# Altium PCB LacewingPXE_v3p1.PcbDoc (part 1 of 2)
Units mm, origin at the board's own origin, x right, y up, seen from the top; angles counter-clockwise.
Board outline 62.74 x 108.59 mm, 2 copper layers (Top Layer, Bottom Layer); 114 components, 91 nets, 539 pads, 84 vias.
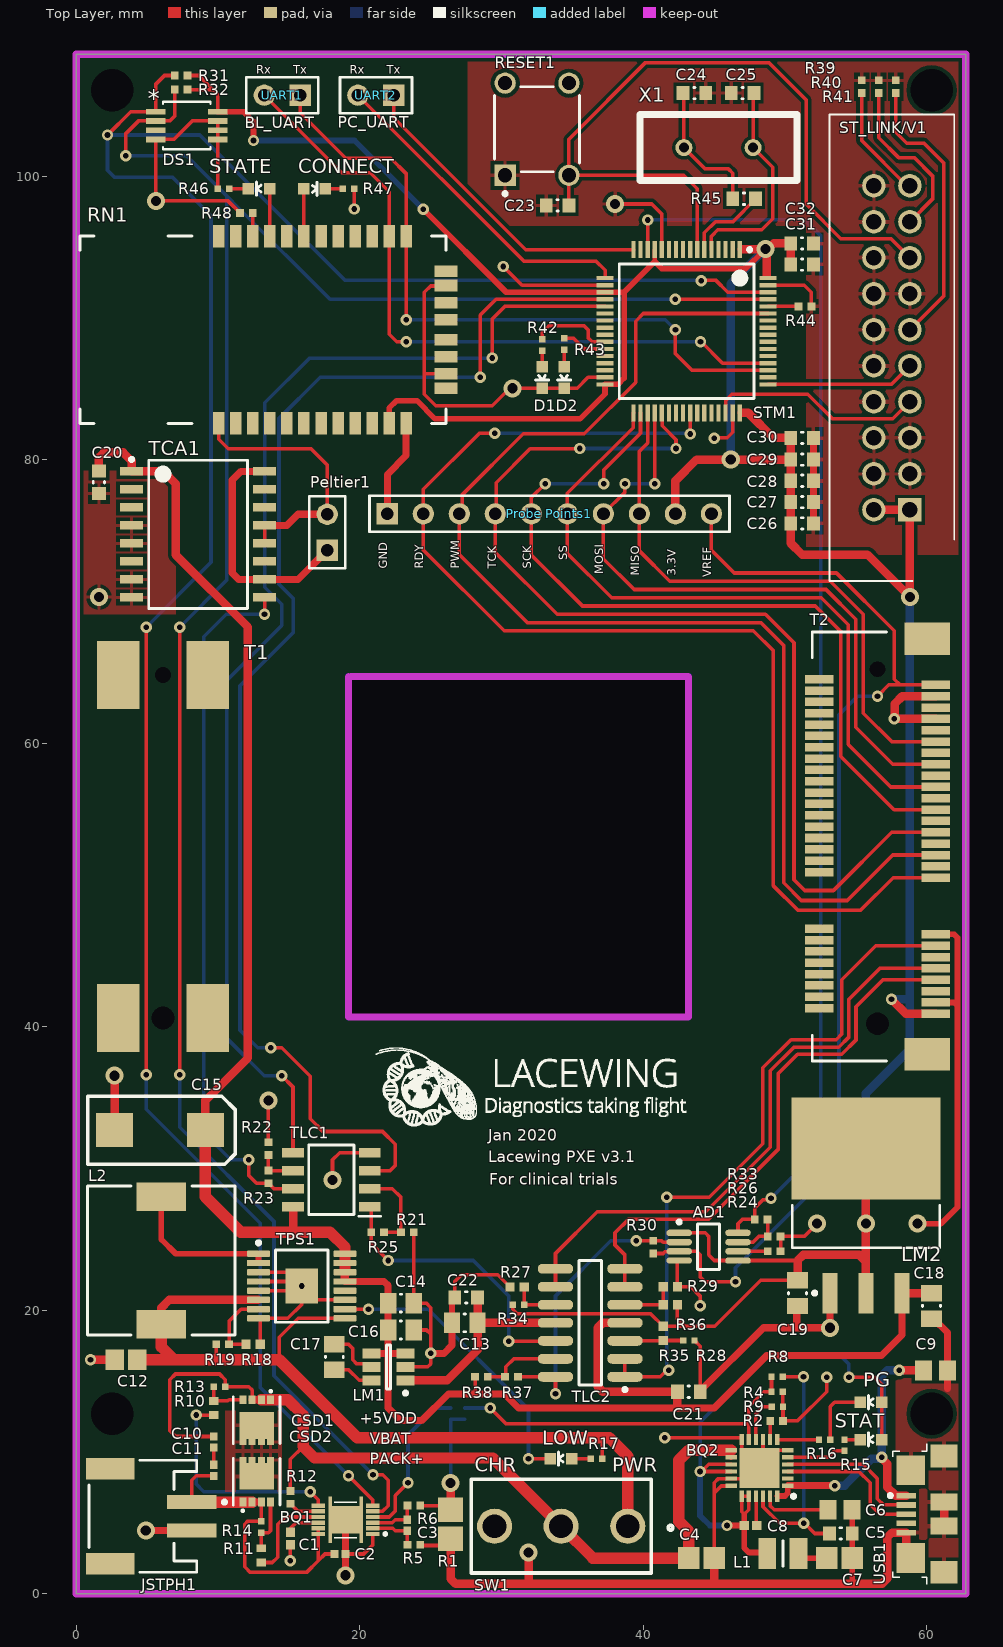
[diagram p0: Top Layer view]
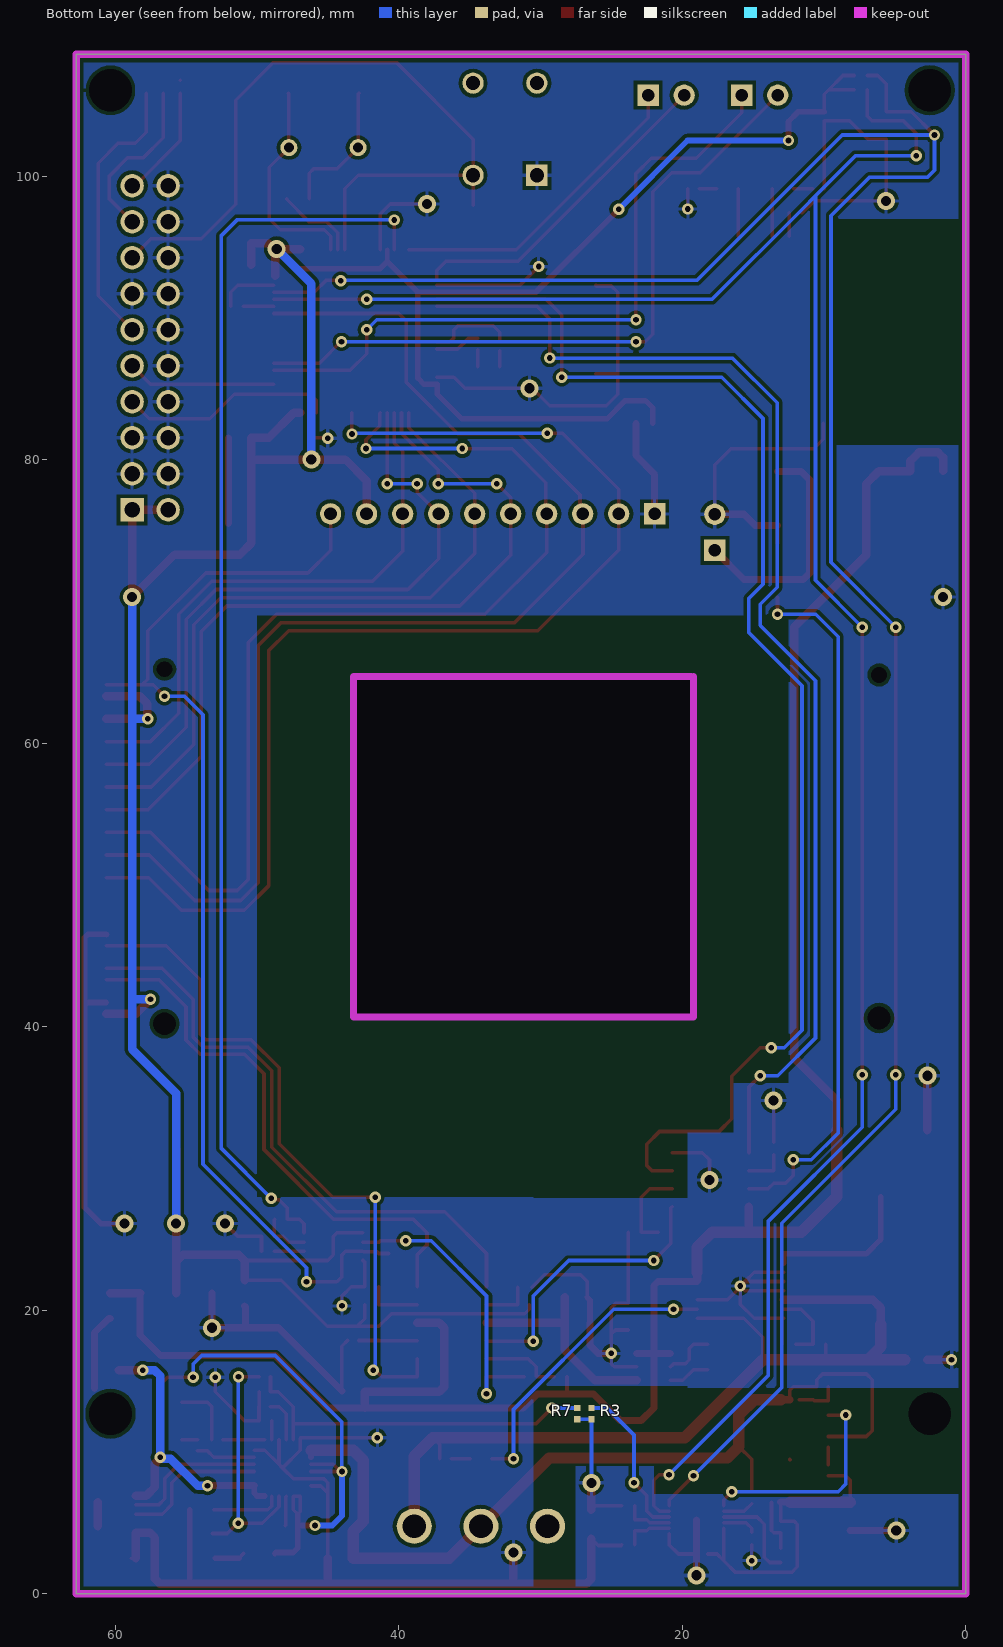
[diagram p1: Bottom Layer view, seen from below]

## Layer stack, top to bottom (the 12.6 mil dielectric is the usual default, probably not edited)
Top Solder: solder mask 0.0102, Solder Resist, Dk 3.5
Top Layer: signal copper 0.0356
Dielectric 1: dielectric 0.32, FR-4, Dk 4.8
Bottom Layer: signal copper 0.0356
Bottom Solder: solder mask 0.0102, Solder Resist, Dk 3.5

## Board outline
0,0 62.738,0 62.738,108.585 0,108.585
cut-out: 43.188,40.672 19.188,40.672 19.188,64.705 43.188,64.705

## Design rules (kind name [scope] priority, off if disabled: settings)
Clearance [All] p1: gap=0.254 ignorepadtopadclearanceinfootprint=TRUE except(0: Arc-Hole Track-Hole SMDPad-Hole THPad-Hole Via-Hole Fill-Hole Poly-Hole Region-Hole Text-Hole; 0.1: Arc-SMDPad Track-SMDPad SMDPad-SMDPad; 0.127: Arc-Arc Arc-Track Track-Track)
ComponentClearance [All] p1 off: gap=0.254 collisioncheckmode=3 verticalgap=0.254 showdistances=FALSE
HoleSize [All] p1: absolutevalues=TRUE maxlimit=3 minlimit=0.025 maxpercent=80.000 minpercent=20.000
MinimumSolderMaskSliver [All] p1: minsoldermaskwidth=0.1
PolygonConnect [All] p1: connectstyle=Relief reliefconductorwidth=0.254 reliefentries=4 polygonreliefangle="90 Angle" airgapwidth=0.254
RoutingVias [All] p1: holewidth=0.711 width=1.27 viastyle="Through Hole" minholewidth=0.4 minwidth=0.8 maxholewidth=0.711 maxwidth=1.27
SilkToSilkClearance [All] p1: silktosilkclearance=0.1
SilkToSolderMaskClearance [IsPad] p1: minsilkscreentomaskgap=0.1 clearancetoexposedcopper=TRUE
SolderMaskExpansion [All] p1: expansion=0.102 istentingtop=FALSE
Width Width_PACK+ [InNet('PACK+')] p1: maxlimit=1 minlimit=0.254 preferedwidth=0.6 minimp=50.000000 maximp=50.000000 favimp=50.000000
Width Width_BAT+ [InNet('BAT+')] p2: maxlimit=1 minlimit=0.254 preferedwidth=0.6 minimp=50.000000 maximp=50.000000 favimp=50.000000
Width Width_+5VDD [InNet('+5VDD')] p3: maxlimit=1 minlimit=0.254 preferedwidth=0.6 minimp=50.000000 maximp=50.000000 favimp=50.000000
Width Width_-5VDD [InNet('-5VDD')] p4: maxlimit=1 minlimit=0.5 preferedwidth=0.6 minimp=50.000000 maximp=50.000000 favimp=50.000000
Width Width_VLi [InNet('VLiPo')] p5: maxlimit=1 minlimit=0.5 preferedwidth=1 minimp=50.000000 maximp=50.000000 favimp=50.000000
Width Width_VPelt [InNet('Vpeltier')] p6: maxlimit=1 minlimit=0.5 preferedwidth=1 minimp=50.000000 maximp=50.000000 favimp=50.000000
Width Width_5VUSB [InNet('5VUSB')] p7: maxlimit=1 minlimit=0.5 preferedwidth=0.6 minimp=50.000000 maximp=50.000000 favimp=50.000000
Width Width_VBAT [InNet('VBAT')] p8: maxlimit=1 minlimit=0.254 preferedwidth=0.6 minimp=50.000000 maximp=50.000000 favimp=50.000000
Width Width_3VDD [InNet('3.3VDD')] p9: maxlimit=0.6 minlimit=0.254 preferedwidth=0.6 minimp=50.000000 maximp=50.000000 favimp=50.000000
Width [All] p10: maxlimit=0.6 minlimit=0.254 preferedwidth=0.254 minimp=50.000000 maximp=50.000000 favimp=50.000000
25 further rules are at their usual default settings.

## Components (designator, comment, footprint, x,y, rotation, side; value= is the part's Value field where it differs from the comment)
AD1 "AD8237" ADI-RM-8_N 44.599,24.475 r0 top
BQ1 "BQ27750DRZT" BQ27510DRZTG3 19,5.213 r90 top
BQ2 "BQ25606RGET" QFN50P400X400X100-25N 48.188,8.872 r180 top
C1 "2.2uF" CAPC1005X55X25NL05T10 15.1,3.9 r90 top
C2 "0.1uF" CAPC1005X56X25LL10T15 18.6,2.8 r180 top
C3 "0.1uF" CAPC1005X56X25LL10T15 23.35,4.825 r90 top
C4 "10uF" CAPC2013X140X50ML20T25 44.105,2.511 r0 top
C5 "4.7µF" CAPC0603(1608)100_N 53.928,4.25 r180 top
C6 "10uF" CAPC2013X95X45NL10T25 53.878,5.925 r180 top
C7 "10uF" CAPC2013X140X50ML20T25 53.828,2.511 r180 top
C8 "47nF" CAPC1005X55X25NL05T10 47.558,4.811 r180 top
C9 "1uF" CAPC2013X95X45NL10T25 60.6,15.752 r180 top
C10 "0.1uF" CAPC1005X56X25LL10T15 9.7,10.7 r270 top
C11 "0.1uF" CAPC1005X56X25LL10T15 9.7,8.7 r90 top
C12 "10uF" CAPC2013X140X50NL20T25 3.5,16.5 r0 top
C13 "10µF" CAPC0805(2012)75_N 27.4,19.1 r180 top
C14 "2.2µF" CAPC0805(2012)75_N 22.9,20.5 r180 top
C15 "220µF" AVX-CAPC7343_V 5.9,32.7 r180 top
C16 "2.2µF" CAPC0805(2012)75_N 22.9,18.6 r180 top
C17 "10µF" CAPC0805(2012)75_N 18.2,16.7 r270 top
C18 "10µF" CAPC0805(2012)75_N 60.325,20.3 r270 top
C19 "10µF" CAPC0805(2012)75_N 50.872,21.2 r270 top
C20 "0.1µF" CAPC0603(1608)100_N 1.6,78.4 r90 top
C21 "0.1µF" CAPC0603(1608)100_N 43.205,14.241 r180 top
C22 "0.1µF" CAPC0603(1608)100_N 27.5,20.9 r0 top
C23 "100nF" CAPC0603(1608)100_N 33.95,97.927 r180 top
C24 "18pF" CAPC0603(1608)100_N 43.6,105.85 r0 top
C25 "18pF" CAPC0603(1608)100_N 47,105.85 r180 top
C26 "4.7uF" CAPC0603(1608)100_N 51.2,75.494 r0 top
C27 "100nF" CAPC0603(1608)100_N 51.2,77 r0 top
C28 "100nF" CAPC0603(1608)100_N 51.2,78.5 r0 top
C29 "100nF" CAPC0603(1608)100_N 51.2,80 r0 top
C30 "100nF" CAPC0603(1608)100_N 51.2,81.53 r0 top
C31 "1uF" CAPC0603(1608)100_N 51.193,93.747 r0 top
C32 "10nF" CAPC0603(1608)100_N 51.193,95.247 r0 top
CONNECT "Green" LED-0603 16.8,99.1 r270 top
CSD1 "CSD17575Q3" CSD16327 12.725,12.245 r180 top
CSD2 "" CSD16327 12.725,7.896 r0 top
D1 "Green" LED-0603 32.863,85.788 r180 top
D2 "Red" LED-0603 34.418,85.788 r180 top
DS1 "DS7505U+" 21-0036K 7.8,103.559 r0 top
JSTPH1 "Li-Poly battery" "JST- S2B-PH-SM4-TB(LF)(SN)-2_V" 4.699,5.461 r270 top
L1 "1uH" INDC2520X120N 49.838,2.836 r0 top
L2 "15uH" "WE-PD 1050" 6,23.5 r90 top
LM1 "LM2776" TI-DBV6_M 22.023,16 r180 top
LM2 "LM1086" KTT0003B_N 55.7,27.4 r90 top
LOW "Red" LED-0603 34.2,9.518 r90 top
Peltier1 "Header 2" HDR1X2 17.7,73.6 r90 top
PG "Yellow" LED-0603 56.06,13.5 r90 top
"Probe Points1" "Header 10" HDR1X10 21.94,76.172 r0 top
R1 "0.001" RESC3216X89X104LL25T25 26.4,4.9 r90 top
R2 "165" RESC1005X40X25NL05T05 49.4,12.19 r180 top
R3 "10K" RESC1005X40X25LL05T05 26.4,12.7 r90 bottom
R4 "30.1K" RESC1005X40X25LL05T05 49.438,14.247 r180 top
R5 "100" RESC1005X40X25NL05T05 23.805,3.46 r180 top
R6 "100" RESC1005X40X25NL05T05 23.805,6.213 r180 top
R7 "10K" RESC1005X40X25LL05T05 27.4,12.7 r270 bottom
R8 "5.23K" RESC1005X40X25LL05T05 49.438,15.3 r0 top
R9 "340" RESC1005X40X25LL05T05 49.449,13.193 r180 top
R10 "5.1K" RESC0402(1005)_N 9.7,13.1 r90 top
R11 "5.1K" RESC0402(1005)_N 13.05,2.7 r90 top
R12 "10" RESC1005X40X25NL05T05 15.1,6.8 r90 top
R13 "10M" RESC1005X40X25LL05T05 10.1,14.6 r0 top
R14 "10M" RESC1005X40X25LL05T05 13.05,4.7 r90 top
R15 "470" RESC1005X40X25LL05T05 54.188,10.472 r90 top
R16 "470" RESC1005X40X25LL05T05 52.788,10.872 r0 top
R17 "470" RESC1005X40X25LL05T05 36.7,9.518 r180 top
R18 "68K" RESC1005X40X25ML05T05 12.47,17.6 r180 top
R19 "330K" RESC1005X40X25NL05T05 10.325,17.6 r0 top
R21 "20k" RESC1005X40X25NL05T05 23.348,25.5 r180 top
R22 "20k" RESC1005X40X25NL05T05 13.551,31.4 r270 top
R23 "10k" RESC1005X40X25NL05T05 13.551,29.4 r270 top
R24 "1k" RESC1005X40X25NL05T05 49.226,24.15 r180 top
R25 "10k" RESC1005X40X25NL05T05 21.25,25.5 r180 top
R26 "1k" RESC1005X40X25NL05T05 49.226,25.2 r180 top
R27 "24k" RESC1005X40X25ML05T05 31.1,21.625 r0 top
R28 "30k" RESC1005X40X25LL05T05 43.205,17.861 r180 top
R29 "51k" RESC1005X40X25ML05T05 41.9,21.65 r180 top
R30 "10k" RESC1005X40X25NL05T05 40.7,24.45 r90 top
R31 "10k" RESC1005X40X25NL05T05 7.4,107.092 r0 top
R32 "10K" RESC1005X40X25NL05T05 7.4,106.092 r0 top
R33 "1M" RESC1005X40X25NL05T05 48.3,26.4 r180 top
R34 "75k" RESC1005X40X25LL05T05 31.188,20.38 r180 top
R35 "51k" RESC1005X40X25ML05T05 41.4,18.361 r90 top
R36 "51k" RESC1005X40X25ML05T05 41.905,20.38 r0 top
R37 "20k" RESC1005X40X25NL05T05 30.7,15.3 r0 top
R38 "20k" RESC1005X40X25NL05T05 28.578,15.3 r0 top
R39 "10k" RESC1005X40X25NL05T05 55.4,106.3 r270 top
R40 "10k" RESC1005X40X25NL05T05 56.6,106.3 r270 top
R41 "10k" RESC1005X40X25NL05T05 57.8,106.3 r270 top
R42 "470" RESC1005X40X25LL05T05 32.863,88.081 r90 top
R43 "470" RESC1005X40X25LL05T05 34.418,88.142 r90 top
R44 "10k" RESC1005X40X25NL05T05 51.4,90.8 r180 top
R45 "0" RESC0603(1608)_N 47.1,98.4 r0 top
R46 "470" RESC1005X40X25LL05T05 10.384,99.1 r0 top
R47 "470" RESC1005X40X25LL05T05 19.2,99.1 r180 top
R48 "10k" RESC1005X40X25NL05T05 12,97.4 r0 top
RESET1 "Tactile switch" OMRON-B3F-1000-4_V 32.5,103.3 r90 top
RN1 "Bluetooth module w/ antenna" RN41 18.071,89.154 r0 top
ST_LINK/V1 "JTAG Programmer" JTAG2 58.801,76.454 r90 top
STAT "Green" LED-0603 56.06,10.872 r90 top
STATE "Red" LED-0603 12.9,99.1 r90 top
STM1 "STM32F303RET6" STM-LQFP64_V 43.05,89.05 r270 top
SW1 "" 1000-SERIES(SPDT) 34.2,4.761 r90 top
T1 "Mini PCIe Latch" "Molex Latch-48099" 6.115,52.705 r90 top
T2 "Mini PCIe connector" "Molex Conn-67910" 56.515,52.705 r90 top
TCA1 "TCA0372 Dual high power Op-amp" ONSC-SOIC-16-751G-03_V 8.59,74.725 r0 top
TLC1 "TLC2272AID" SOIC127P600X175-8N 18,29.2 r180 top
TLC2 "TLC2274 Quad Op-amp" TI-D14_M 36.25,19.11 r180 top
TPS1 "TPS61032" PW0016A_M 15.9,21.7 r0 top
UART1 "BL_UART" HDR1X2 15.8,105.7 r180 top
UART2 "PC_UART" HDR1X2 22.4,105.7 r180 top
USB1 "ZX62R-B-5P" HIRO-ZX62R-B-5P_V 59.876,5.611 r90 top
X1 "8MHz" QCL 45.3,102 r180 top

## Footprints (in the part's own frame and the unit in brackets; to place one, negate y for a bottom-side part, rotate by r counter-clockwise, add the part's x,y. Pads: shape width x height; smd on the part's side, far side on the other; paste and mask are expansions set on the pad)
21-0036K [mil]
  rect 54x16 smd paste+0 mask+0: 1(-86,38.39) 2(-86,12.8) 3(-86,-12.8) 4(-86,-38.39) 5(86,-38.39) 6(86,-12.8) 7(86,12.8) 8(86,38.39)
  silkscreen extent -66,-66 66,66, body extent 0,0 10,10, height 10
1000-SERIES(SPDT) [mm]
  round 2.48 hole 1.68: 1(0,-4.7) 2(0,0) 3(0,4.7)
  silkscreen extent -3.3,-7.88 3.3,6.35
ADI-RM-8_N [mm] "SOP, 8-Leads, Body 3x3mm, Pitch 0.65mm, IPC Medium Density"
  oval 1.8x0.45 smd: 1(-2.075,0.975) 2(-2.075,0.325) 3(-2.075,-0.325) 4(-2.075,-0.975) 5(2.075,-0.975) 6(2.075,-0.325) 7(2.075,0.325) 8(2.075,0.975)
  silkscreen extent -2.2,-1.6 0.77,1.87, body extent -1.6,-1.6 1.6,1.6, height 1.1
AVX-CAPC7343_V [mm] "SMT Capacitor, 2 Leads, Body 7.3x4.3mm"
  rect 2.6x2.4 smd: 1(-3.202,0.007) 2(3.198,0.007)
  silkscreen extent -5.33,-2.39 5.08,2.41, body extent -3.49,-2.03 3.51,2.04, height 4.05
BQ27510DRZTG3 [mm]
  rect 0.3x0.95 smd: 1(-1,-1.925) 2(-0.6,-1.925) 3(-0.2,-1.925) 4(0.2,-1.925) 5(0.6,-1.925) 6(1,-1.925) 7(1,1.925) 8(0.6,1.925) 9(0.2,1.925) 10(-0.2,1.925) 11(-0.6,1.925) 12(-1,1.925)
  rect 1.95x2.45 smd: 13(0,0)
  rect 0.675x0.25 smd: 14(-1.313,1.1) 15(-1.313,-1.1) 16(1.313,1.1) 17(1.313,-1.1)
  silkscreen extent -1.25,-2.9 1.25,0.8
CAPC0603(1608)100_N [mm] "Chip Capacitor, Body 1.6x0.8mm, Height 1.0mm, IPC Medium Density"
  rect 0.9x1 smd: 1(-0.8,0) 2(0.8,0)
  silkscreen extent -0.05,-0.4 0.05,0.4, body extent -0.87,-0.48 0.88,0.47, height 1
CAPC0805(2012)75_N [mm] "Chip Capacitor, Body 2.0x1.2mm, Height 0.75mm, IPC Medium Density"
  rect 1.15x1.45 smd: 1(-0.9,0) 2(0.9,0)
  silkscreen extent -0.05,-0.62 0.05,0.63, body extent -1.1,-0.72 1.1,0.73, height 0.75
CAPC1005X55X25NL05T10 [mm] "Chip Capacitor, 2-Leads, Body 1.05x0.55mm, IPC Medium Density"
  rect 0.66x0.62 smd: 1(-0.44,0) 2(0.44,0)
  body extent -0.53,-0.28 0.53,0.28, height 0.55
CAPC1005X56X25LL10T15 [mm] "Chip Capacitor, 2-Leads, Body 1.00x0.50mm, IPC High Density"
  rect 0.58x0.54 smd: 1(-0.39,0) 2(0.39,0)
  body extent -0.55,-0.3 0.55,0.3, height 0.56
CAPC2013X95X45NL10T25 [mm] "Chip Capacitor, 2-Leads, Body 2.00x1.25mm, IPC Medium Density"
  rect 1.2x1.4 smd: 1(-0.85,0) 2(0.85,0)
  body extent -1.05,-0.67 1.05,0.67, height 0.95
CAPC2013X140X50ML20T25 [mm] "Chip Capacitor, 2-Leads, Body 2.00x1.25mm, IPC Low Density"
  rect 1.5x1.55 smd: 1(-0.9,0) 2(0.9,0)
  body extent -1.1,-0.72 1.1,0.72, height 1.4
CAPC2013X140X50NL20T25 [mm] "Chip Capacitor, 2-Leads, Body 2.00x1.25mm, IPC Medium Density"
  rect 1.3x1.45 smd: 1(-0.8,0) 2(0.8,0)
  body extent -1.1,-0.72 1.1,0.72, height 1.4
CSD16327 [mm] "CSD17575Q3"
  rect 0.5x0.63 smd: 1(-0.975,-1.435) 2(-0.325,-1.435) 3(0.325,-1.435) 4(0.975,-1.435)
  rect 0.5x0.41 smd: 5(0.975,1.545) 6(0.325,1.545) 7(-0.325,1.545) 8(-0.975,1.545)
  rect 2.45x1.9 smd: 9(0,0.39)
  silkscreen extent -1.65,-2.08 1.65,1.65
HDR1X2 [mm] "Connector; Header; 2 Position"
  rect 1.5x1.5 hole 0.9: 1(0,0)
  round 1.5 hole 0.9: 2(2.54,0)
  silkscreen extent -1.27,-1.27 3.81,1.27
HDR1X10 [mm] "Connector; Header; 10 Position"
  rect 1.5x1.5 hole 0.9: 1(0,0)
  round 1.5 hole 0.9: 2(2.54,0) 3(5.08,0) 4(7.62,0) 5(10.16,0) 6(12.7,0) 7(15.24,0) 8(17.78,0) 9(20.32,0) 10(22.86,0)
  silkscreen extent -1.27,-1.27 24.13,1.27
HIRO-ZX62R-B-5P_V [mm] "USB Micro-B R/A Connector"
  rect 0.4x1.35 smd: 1(1.3,1.338) 2(0.65,1.338) 3(0,1.338) 4(-0.65,1.338) 5(-1.3,1.338)
  rect 2.1x2 smd: 6(-3.1,1.012) 11(3.1,1.012)
  rect 1.6x1.9 smd: 7(-4.1,-1.338) 10(4.1,-1.338)
  rect 1.2x1.9 smd: 8(-0.85,-1.338) 9(0.85,-1.338)
  silkscreen extent -4.95,-0.13 4.95,2.58, body extent -4.4,-3.95 4.4,1.78, height 2.71
INDC2520X120N [mm]
  rect 1.25x2.2 smd: 1(-1.1,0) 2(1.1,0)
  silkscreen extent 0,-0.9 0,0.9, body extent -1.25,-1 1.25,1, height 1.2
"JST- S2B-PH-SM4-TB(LF)(SN)-2_V" [mm] "SMD, 2-Leads, Body 7.9x7.6mm, Pitch 2mm"
  rect 1x3.5 smd: 1(-1,3.45) 2(1,3.45)
  rect 1.5x3.4 smd: MP1(-3.35,-2.3) MP2(3.35,-2.3)
  silkscreen extent -3.95,-3.8 3.95,5.88, body extent -3.95,-3.8 3.95,4.8, height 5.6
JTAG2 [mm] "Header, Vertical Shrouded, 100 mil pitch; 25 mil lead width, 20 pins, 2 rows, 10 pins per row, 1295 mil L X 346 mil W X 346 mil H body"
  rect 1.652x1.652 hole 1.101 paste-1.652: 1(0,0)
  round 1.652 hole 1.101 paste-1.652: 2(0,2.54) 3(2.54,0) 4(2.54,2.54) 5(5.08,0) 6(5.08,2.54) 7(7.62,0) 8(7.62,2.54) 9(10.16,0) 10(10.16,2.54) 11(12.7,0) 12(12.7,2.54) 13(15.24,0) 14(15.24,2.54) 15(17.78,0) 16(17.78,2.54) 17(20.32,0) 18(20.32,2.54) 19(22.86,0) 20(22.86,2.54)
  silkscreen extent -5.02,-3.12 27.88,5.66, body extent -3.18,-3.56 26.04,5.92, height 8.89
KTT0003B_N [mm] "D2-PAK, 3-Leads, Body 10.41x8.89mm, Pitch 2.54mm, IPC Medium Density"
  rect 2.85x1.05 smd: 1(-6.2,2.54) 2(-6.2,0) 3(-6.2,-2.54)
  rect 7.2x10.5 smd: 4(4,0)
  silkscreen extent -6.32,-5.2 0,5.2, body extent -6.78,-5.2 7.57,5.2, height 4.64
LED-0603 [mil] "LED-0603"
  rect 32x32 smd: A(0,-29.53) C(0,30)
  silkscreen extent -18,-6 19,7
"Molex Conn-67910" [mm] "Board-to-Board Connector, SMT, Right Angle, Pitch 0.8mm, 52-Position, Female"
  rect 0.6x2 smd: 1(-11.8,-4.1) 2(-11.4,4.1) 3(-11,-4.1) 4(-10.6,4.1) 5(-10.2,-4.1) 6(-9.8,4.1) 7(-9.4,-4.1) 8(-9,4.1) 9(-8.6,-4.1) 10(-8.2,4.1) 11(-7.8,-4.1) 12(-7.4,4.1) 13(-7,-4.1) 14(-6.6,4.1) 15(-6.2,-4.1) 16(-5.8,4.1) 17(-2.2,-4.1) 18(-1.8,4.1) 19(-1.4,-4.1) 20(-1,4.1) 21(-0.6,-4.1) 22(-0.2,4.1) 23(0.2,-4.1) 24(0.6,4.1) 25(1,-4.1) 26(1.4,4.1) 27(1.8,-4.1) 28(2.2,4.1) 29(2.6,-4.1) 30(3,4.1) 31(3.4,-4.1) 32(3.8,4.1) 33(4.2,-4.1) 34(4.6,4.1) 35(5,-4.1) 36(5.4,4.1) 37(5.8,-4.1) 38(6.2,4.1) 39(6.6,-4.1) 40(7,4.1) 41(7.4,-4.1) 42(7.8,4.1) 43(8.2,-4.1) 44(8.6,4.1) 45(9,-4.1) 46(9.4,4.1) 47(9.8,-4.1) 48(10.2,4.1) 49(10.6,-4.1) 50(11,4.1) 51(11.4,-4.1) 52(11.8,4.1)
  round 1.3 hole 1.6 unplated: MH1(-12.5,0)
  round 0.8 hole 1.1 unplated: MH2(12.5,0)
  rect 2.3x3.2 smd: MP1C(-14.65,-3.5) MP2C(14.65,-3.5)
  silkscreen extent -15.12,-0.64 15.12,4.6, body extent -15,-5 15,4.5, height 5.6
"Molex Latch-48099" [mm]
  round 1.3 hole 1.6 unplated: MH3(-12.1,0)
  round 0.8 hole 1.1 unplated: MH4(12.1,0)
  rect 4.8x3 smd: MP1L(-12.1,3.15) MP2L(-12.1,-3.15) MP3L(12.1,3.15) MP4L(12.1,-3.15)
OMRON-B3F-1000-4_V [mm] "TH, 4-Leads, Body 6x6mm"
  rect 1.5x1.5 hole 1 paste+0: 1(-3.25,2.25)
  round 1.5 hole 1 paste+0: 2(3.25,2.25) 3(-3.25,-2.25) 4(3.25,-2.25)
  silkscreen extent -4.67,-3 3,3, body extent -3,-3 3,3, height 4.5
ONSC-SOIC-16-751G-03_V [mm] "SOIC, 16-Leads, Body 10.45x7.6mm, Pitch 1.27mm"
  rect 1.62x0.58 smd: 1(-4.69,4.445) 2(-4.69,3.175) 3(-4.69,1.905) 4(-4.69,0.635) 5(-4.69,-0.635) 6(-4.69,-1.905) 7(-4.69,-3.175) 8(-4.69,-4.445) 9(4.69,-4.445) 10(4.69,-3.175) 11(4.69,-1.905) 12(4.69,-0.635) 13(4.69,0.635) 14(4.69,1.905) 15(4.69,3.175) 16(4.69,4.445)
  silkscreen extent -4.81,-5.23 3.48,5.41, body extent -3.8,-5.23 3.8,5.23, height 2.65
PW0016A_M [mm] "SOP, 16-Leads, Body 5.1x4.5mm, Pitch 0.65mm, IPC Low Density"
  rrect22% 1.6x0.45 smd: 1(-3.05,2.275) 2(-3.05,1.625) 3(-3.05,0.975) 4(-3.05,0.325) 5(-3.05,-0.325) 6(-3.05,-0.975) 7(-3.05,-1.625) 8(-3.05,-2.275) 9(3.05,-2.275) 10(3.05,-1.625) 11(3.05,-0.975) 12(3.05,-0.325) 13(3.05,0.325) 14(3.05,0.975) 15(3.05,1.625) 16(3.05,2.275)
  rect 2.31x2.46 smd: PowerPAD(0,0)
  silkscreen extent -3.17,-2.55 1.85,3.17, body extent -3.21,-2.5 3.21,2.5, height 1
QCL [mm]
  round 1.2 hole 0.7: 1(-2.44,0) 2(2.44,0)
  silkscreen extent -5.53,-2.32 5.53,2.32
QFN50P400X400X100-25N [mm]
  rect 0.8x0.3 smd: 1(-2,1.25) 2(-2,0.75) 3(-2,0.25) 4(-2,-0.25) 5(-2,-0.75) 6(-2,-1.25) 13(2,-1.25) 14(2,-0.75) 15(2,-0.25) 16(2,0.25) 17(2,0.75) 18(2,1.25)
  rect 0.3x0.8 smd: 7(-1.25,-2) 8(-0.75,-2) 9(-0.25,-2) 10(0.25,-2) 11(0.75,-2) 12(1.25,-2) 19(1.25,2) 20(0.75,2) 21(0.25,2) 22(-0.25,2) 23(-0.75,2) 24(-1.25,2)
  rect 2.8x2.8 smd: 25(0,0)
  silkscreen extent -2.53,1.88 -2.28,2.12, body extent -2.05,-2.05 2.05,2.05, height 1
RESC0402(1005)_N [mm] "Chip Resistor, Body 1.0x0.5mm, IPC Medium Density"
  rect 0.55x0.65 smd: 1(-0.5,0) 2(0.5,0)
  body extent -0.52,-0.27 0.53,0.28, height 0.4
RESC0603(1608)_N [mm] "Chip Resistor, Body 1.6x0.8mm, IPC Medium Density"
  rect 0.9x1 smd: 1(-0.8,0) 2(0.8,0)
  silkscreen extent -0.05,-0.4 0.05,0.4, body extent -0.85,-0.47 0.85,0.47, height 0.6
RESC1005X40X25LL05T05 [mm] "Chip Resistor, 2-Leads, Body 1.00x0.50mm, IPC High Density"
  rect 0.45x0.45 smd: 1(-0.4,0) 2(0.4,0)
  body extent -0.53,-0.27 0.53,0.28, height 0.4
RESC1005X40X25ML05T05 [mm] "Chip Resistor, 2-Leads, Body 1.00x0.50mm, IPC Low Density"
  rect 0.65x0.65 smd: 1(-0.5,0) 2(0.5,0)
  body extent -0.53,-0.27 0.53,0.28, height 0.4
RESC1005X40X25NL05T05 [mm] "Chip Resistor, 2-Leads, Body 1.00x0.50mm, IPC Medium Density"
  rect 0.55x0.55 smd: 1(-0.45,0) 2(0.45,0)
  body extent -0.53,-0.27 0.53,0.28, height 0.4
RESC3216X89X104LL25T25 [mm] "Chip Resistor, 2-Leads, Body 3.45x1.85mm, IPC High Density"
  rect 1.7x1.75 smd: 1(-1.025,0) 2(1.025,0)
  body extent -1.73,-0.92 1.73,0.92, height 0.89
RN41 [mil]
  rect 32x63 smd: 1(-315.42,-259.92) 2(-268.18,-259.92) 3(-220.93,-259.92) 4(-173.69,-259.92) 5(-126.44,-259.92) 6(-79.2,-259.92) 7(-31.58,-259.92) 8(15.42,-259.92) 9(63.42,-259.92) 10(110.42,-259.92) 11(157.42,-259.92) 12(204.42,-259.92) 13(204.42,259.92) 14(157.42,259.92) 15(110.42,259.92) 16(63.42,259.92) 17(15.42,259.92) 18(-31.58,259.92) 19(-79.2,259.92) 20(-126.44,259.92) 21(-173.69,259.92) 22(-220.93,259.92) 23(-268.18,259.92) 24(-315.42,259.92)
  rect 63x32 smd: 28(315.42,122.92) 29(315.42,-122.13) 30(315.42,162.92) 31(315.42,74.92) 32(315.42,27.92) 33(315.42,-27.64) 34(315.42,-74.88) 35(315.42,-162.37)
  silkscreen extent -701,-260 315,260
SOIC127P600X175-8N [mm]
  rect 1.525x0.65 smd: 1(-2.712,1.905) 2(-2.712,0.635) 3(-2.712,-0.635) 4(-2.712,-1.905) 5(2.712,-1.905) 6(2.712,-0.635) 7(2.712,0.635) 8(2.712,1.905)
  silkscreen extent -3.47,-2.45 1.6,2.58, body extent -3,-2.45 3,2.45, height 1.75
STM-LQFP64_V [mm] "Thin QFP, 64-Leads, Body 10x10mm, Pitch 0.5mm, ST Recommended"
  rect 1.2x0.3 smd: 1(-5.75,3.75) 2(-5.75,3.25) 3(-5.75,2.75) 4(-5.75,2.25) 5(-5.75,1.75) 6(-5.75,1.25) 7(-5.75,0.75) 8(-5.75,0.25) 9(-5.75,-0.25) 10(-5.75,-0.75) 11(-5.75,-1.25) 12(-5.75,-1.75) 13(-5.75,-2.25) 14(-5.75,-2.75) 15(-5.75,-3.25) 16(-5.75,-3.75) 33(5.75,-3.75) 34(5.75,-3.25) 35(5.75,-2.75) 36(5.75,-2.25) 37(5.75,-1.75) 38(5.75,-1.25) 39(5.75,-0.75) 40(5.75,-0.25) 41(5.75,0.25) 42(5.75,0.75) 43(5.75,1.25) 44(5.75,1.75) 45(5.75,2.25) 46(5.75,2.75) 47(5.75,3.25) 48(5.75,3.75)
  rect 0.3x1.2 smd: 17(-3.75,-5.75) 18(-3.25,-5.75) 19(-2.75,-5.75) 20(-2.25,-5.75) 21(-1.75,-5.75) 22(-1.25,-5.75) 23(-0.75,-5.75) 24(-0.25,-5.75) 25(0.25,-5.75) 26(0.75,-5.75) 27(1.25,-5.75) 28(1.75,-5.75) 29(2.25,-5.75) 30(2.75,-5.75) 31(3.25,-5.75) 32(3.75,-5.75) 49(3.75,5.75) 50(3.25,5.75) 51(2.75,5.75) 52(2.25,5.75) 53(1.75,5.75) 54(1.25,5.75) 55(0.75,5.75) 56(0.25,5.75) 57(-0.25,5.75) 58(-0.75,5.75) 59(-1.25,5.75) 60(-1.75,5.75) 61(-2.25,5.75) 62(-2.75,5.75) 63(-3.25,5.75) 64(-3.75,5.75)
  silkscreen extent -5.87,-4.75 4.75,4.75, body extent -5,-5 5,5, height 1.6
TI-D14_M [mm] "SOIC, 14-Leads, Body 8.65x3.9mm, Pitch 1.27mm, IPC Low Density"
  oval 2.5x0.7 smd: 1(-2.45,3.81) 2(-2.45,2.54) 3(-2.45,1.27) 4(-2.45,0) 5(-2.45,-1.27) 6(-2.45,-2.54) 7(-2.45,-3.81) 8(2.45,-3.81) 9(2.45,-2.54) 10(2.45,-1.27) 11(2.45,0) 12(2.45,1.27) 13(2.45,2.54) 14(2.45,3.81)
  silkscreen extent -2.58,-4.4 0.8,4.83, body extent -2,-4.38 2,4.38, height 1.75
TI-DBV6_M [mm] "SOT-23, 6-Leads, Body 2.90x1.60mm, Pitch 0.95mm, IPC Low Density"
  rect 1.3x0.7 smd: 1(-1.2,0.95) 2(-1.2,0) 3(-1.2,-0.95) 4(1.2,-0.95) 5(1.2,0) 6(1.2,0.95)
  silkscreen extent -1.33,-1.55 0.15,1.97, body extent -0.87,-1.52 0.87,1.53, height 1.45
"WE-PD 1050" [mm] "SMD Inductor, 2-Leads, Body 10,0x10,0mm"
  rect 2x3.5 smd: 1(-4.5,0) 2(4.5,0)
  silkscreen extent -5.25,-5.2 5.25,5.2, body extent -5,-5 5,5, height 4.75

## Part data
BQ1: "Gas Gauge and Protection Solution for 1 Series", Manufacturer="Texas Instruments"
BQ2: "Battery Charger", Manufacturer="Texas Instruments"
C1: library part CMP-2008-04630-4, "CAP 0402", Manufacturer=Murata, Part No=GRM155R60J225KE95D
C2 C3 C10 C11: library part CMP-2008-02743-1, "CAP 0402", Manufacturer=AVX, Part Number=04026D104KAT2A
C4 C7: library part CMP-2007-04702-1, "CAP 0805", Manufacturer=AVX, Part No=0805ZC106KAT2A
C5: library part CAP, "Cap 0603", Manufacturer=Murata, Part No=GRM188R61C475KAAJD
C6: library part CMP-2007-00191-1, "CAP 0805", Manufacturer=Murata, Part No=GRM21BC71E106KE11L
C8: library part CMP-2008-04630-4, "CAP 0402", Manufacturer=Murata, Part No=GRM155R71E473KA88D
C9: library part CMP-2007-00191-1, "CAP 0805", Manufacturer=Murata, Part No=GRM219R71E105KA88D
C12: library part CMP-2007-04643-1, "CAP 0805", Manufacturer=AVX, Part No=08056D106KAT2A
C13 C17 C18 C19: library part CMP-1036-00002-1, "CAP 0805", Manufacturer="Wurth Electronics", Part No=885012107010
C14 C16: library part CMP-1036-00002-1, "CAP 0805", Manufacturer=Multicomp, Part No=MC0805B225K250CT
C15: library part CMP-0279-00002-1, "Capacitor, Tantalum, 220uF 10% 10V MCCT-D (7343-31)", Manufacturer=AVX, Part No=TAJD227K010RNJ
C20 C21 C22: library part CAP, "Ceramic CAP0603 (1608 Metric) Thickness 1mm SMD", Case-EIA=0603
C23 C24 C25 C26 C27 C28 C29 C30 C31 C32: library part CMP-1035-00032-1, "Ceramic CAP0603 (1608 Metric) Thickness 1mm SMD", Case-EIA=0603
CONNECT D1: library part LED0603, "LED SMD 0603", Manufacturer=KingBright, Part No=KPT-1608SGC
CSD1: "MOSFET Transistor for Fuel Gauge", Manufacturer="Texas Instruments", Part No=CSD17575Q3T
CSD2: library part CSD17575Q3, "MOSFET Transistor for Fuel Gauge", Manufacturer="Texas Instruments", Part No=CSD17575Q3T
D2 LOW STATE: library part LED0603, "LED SMD 0603", Manufacturer=KingBright, Part No=KPT-1608SECK-J3
DS1: library part ds7505u+, "Digital Thermometer and Thermostat", Manufacturer=Maxim
JSTPH1: library part CN-1P-2M-R2, "Wire-To-Board Connector", Manufacturer=JST, Part No=S2B-PH-SM4-TB(LF)(SN)
L1: library part DFE252012F-1R0M=P2, "1uH Inductor", Manufacturer=Murata, Part No=DFE252012F-1R0M{}P2
L2: library part CMP-1396-00032-1, "Power Inductor", Manufacturer="Wurth Elektronik", Part No=7447714150
LM1: Manufacturer="Texas Instruments", Part No=LM2776DBVT
LM2: library part CMP-0062-00552-5, "1.5A Low Dropout Positive Regulators, 3-pin TO-263, Pb-Free", Manufacturer="Texas Instruments", Part No=LM1086IS-3.3/NOPB
Peltier1: "Header, 2-Pin"
PG: library part LED0603, "LED SMD 0603", Manufacturer=Kingbright, Part No=KPT-1608SYCK-J3
"Probe Points1": "Header, 10-Pin"
R1: library part CMP-1666-00018-2, "RES 1206", Manufacturer=Vishay, Part No=WSLP12061L000FEA
R2: library part CMP-2002-08233-1, Manufacturer="Vishay Dale", Part No=CRCW0402165RFKED
R3: library part CMP-2002-01179-1, "Thermistor RES 0402", Manufacturer=Panasonic, Part Number=ERTJ0EG103FA
R4: library part CMP-2002-08506-3, "RES 0402", Manufacturer=Vishay, Part No=CRCW040230K1FKED
R5 R6: library part CMP-2002-08127-1, "RES 0402", Manufacturer=Vishay, Part No=CRCW0402100RFKED
R7: library part CMP-2002-01179-1, "Thermistor RES 0402", Manufacturer=Panasonic, Part No=ERTJ0EG103FA
R8: library part CMP-2002-00118-3, "RES 0402", Manufacturer=Vishay, Part No=CRCW04025K23FKED
R9: library part CMP-2002-00876-1, "RES 0402", Manufacturer=Panasonic, Part No=ERJ2RKF3400X
R10 R11: library part CMP-1011-00590-1, "RES 0402", Manufacturer=Vishay, Part No=CRCW04025K10FKED
R12: library part CMP-2002-08143-1, "RES 0402", Manufacturer="Vishay Dale", Part No=CRCW040210R0FKED
R13 R14: library part CMP-2002-08141-1, "RES 0402", Manufacturer=Vishay, Part No=CRCW040210M0FKED
R15 R16 R17 R42 R43 R46 R47: library part CMP-2002-00022-1, "RES 0402", Manufacturer=Vishay, Part No=CRCW0402470RFKED
R18: library part CMP-2002-00170-1, "RES 0402", Manufacturer=Vishay, Part No=CRCW040268K0FKED
R19: library part CMP-2002-08521-1, "RES 0402", Manufacturer=Vishay, Part No=CRCW0402330KFKED
R21 R22 R37 R38: library part CMP-2002-08356-1, "RES 0402", Manufacturer=Vishay, Part No=CRCW040220K0FKED
R23 R25 R30 R31 R32 R39 R40 R41 R44 R48: library part CMP-2002-08135-1, "RES 0402", Manufacturer=Vishay, Part No=CRCW040210K0FKED
R24 R26: library part CMP-2002-08276-1, "RES 0402", Manufacturer=Vishay, Part No=CRCW04021K00FKED
R27: library part CMP-2002-08403-1, "RES 0402", Manufacturer="Vishay Dale", Part No=CRCW040224K0FKED
R28: library part CMP-2002-08504-1, "RES 0402", Manufacturer="Vishay Dale", Part No=CRCW040230K0FKED
R29 R35 R36: library part CMP-2002-00078-1, "RES 0402", Manufacturer="Vishay Dale", Part Number=CRCW040251K0FKED
R33: library part CMP-2002-08314-1, "RES 0402", Manufacturer=Vishay, Part No=CRCW04021M00FKED
R34: library part CMP-2002-00208-1, "RES 0402", Manufacturer="Vishay Dale", Part No=CRCW040275K0FKED
R45: library part CMP-1012-00514-1, "RES0603 (1608 Metric)  SMD", Case-EIA=0603
RESET1: library part SW-SPST-4_A, "ORMON B3F-10XX"
RN1: library part BLUETOOTH-RN41, "Bluetooth SMD module"
ST_LINK/V1: library part JTAG
STAT: library part LED0603, "LED SMD 0603", Manufacturer=Kingbright, Part No=KPT-1608SGC
STM1: library part STM32F303RBT6_1, "ARM Cortex-M4 32-bit MCU, 128 KB Flash, 32 KB Internal RAM, 52 I/Os, 64-pin LQFP, -40 to 85 degC, Tray", I/Os (High Current)=52, Operating Frequency(F) (Processor speed) (MHz)=72, PartNumber=STM32F303RBT6, Supplier Part Number 1=STM32F303RBT6-ND, Supply Voltage(Vcc) min (V)=2
SW1: library part 1101M1S3ZQE2, "Slide Switch SPDT", Manufacturer="C & K COMPONENTS"
TCA1: library part TCA0372
TLC1: "Integrated Circuit", Manufacturer_Name="Texas Instruments", Mouser Part Number=595-TLC2272AID, RS Part Number=4621437P
TLC2: library part TLC2274
TPS1: Manufacturer=TPS61032PWPR
UART1 UART2: library part "Header 2", "Header, 2-Pin"
USB1: library part CMP-0031-00001-1, "Connector; USBMicro-B,Reverse type, SMT; 5 Position; Right Angle", Manufacturer=Hirose, Part No=ZX62R-B-5P(30)
X1: library part XTAL, "Crystal Oscillator"

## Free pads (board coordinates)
  round 1.524 hole 3 unplated: MH3(2.54,12.7) MH3(2.54,106.045) MH3(60.325,12.7) MH3(60.325,106.045)

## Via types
v1: diameter 0.8, hole 0.4, Top Layer to Bottom Layer, 66 vias
v2: diameter 1.27, hole 0.711, Top Layer to Bottom Layer, 18 vias

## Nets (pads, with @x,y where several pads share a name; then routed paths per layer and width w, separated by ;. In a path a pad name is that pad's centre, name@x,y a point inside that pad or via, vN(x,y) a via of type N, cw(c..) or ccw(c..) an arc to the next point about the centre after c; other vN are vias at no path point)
3.3VDD: "Probe Points1.9" AD1.1 AD1.5 C19.1 C26.1 C27.1 C28.1 C29.1 C30.1 C31.1 C32.1 DS1.8 LM2.2 LM2.4 R31.2 R32.2 R34.2 R35.2 R36.2 RN1.11 ST_LINK/V1.1 ST_LINK/V1.2 STM1.1 STM1.13 STM1.19 STM1.32 STM1.48 STM1.64 T2.1 T2.45 T2.49 | length 252.4
  Top Layer w0.254: R32.2@7.85,106.092 9.659,106.092 ; R31.2@7.85,107.092 8.659,107.092 9.659,106.092 ; DS1.8@9.984,104.534 9.984,105.767 9.659,106.092 ; R34.2@30.788,20.38 30.788,20.075 31.108,19.755 40.505,19.755 R35.2@41.4,18.861 42.939,18.861 ; R36.2@42.405,20.38 42.4,20.375 42.4,19.4 42.939,18.861 ; AD1.1@42.524,25.45 44.355,25.45 44.605,25.2 44.605,23.896 45,23.5 50.872,23.5 ; C19.1@50.872,22.1 48.271,22.1 45.032,18.861 42.939,18.861
  Top Layer w0.3: 40.8,93.957 STM1.13@40.8,94.8
  Top Layer w0.4: DS1.8@9.984,104.534 9.988,104.531 11.811,104.531 12.5,103.842 v1(12.5,102.5) ; RN1.11@22.069,82.552 22.069,83.625 22.6,84.156 24.021,84.156 25.31,82.867 35.525,82.867 37.288,84.63 37.288,85.288 STM1.32@37.3,85.3 38.2,85.3 38.643,85.743 38.643,91.8 ; v1(24.48,97.646) 30.326,91.8 STM1.19@37.3,91.8 38.643,91.8 ; v2@48.576,94.824 47.217,93.464 41.294,93.464 40.8,93.957 38.643,91.8
  Top Layer w0.6: 42.26,76.172 42.26,78.509 43.751,80 v2(46.163,80) C29.1@50.4,80 ; 46.95,83.304 47.4,83.304 49.174,81.53 C30.1@50.4,81.53 C29.1@50.4,80 ; 46.95,94.824 48.576,94.824 v2(48.6,94.847) ; 48.7,92.95 48.7,94.747 v2(48.6,94.847) ; C31.1@50.393,93.747 C32.1@50.393,95.247 49.181,95.247 48.781,94.847 v2(48.6,94.847) ; C19.1@50.872,22.1 50.872,23.5 51.272,23.9 55.209,23.9 55.7,23.409 ; LM2.2@55.7,21.2 55.7,23.409 ; LM2.4@55.7,31.4 v2(55.7,26.1) 55.7,23.409 ; ST_LINK/V1.2@56.261,76.454 ST_LINK/V1.1@58.801,76.454 v2(58.8,70.3) ; v1(57.5,41.924) 58.519,40.905 T2.1@60.615,40.905 ; v2(58.8,70.3) 55.8,73.3 51.197,73.3 50.4,74.097 C26.1@50.4,75.494 C27.1@50.4,77 C28.1@50.4,78.5 C29.1@50.4,80 ; T2.45@60.615,61.705 v1(57.7,61.705) 57.738,61.743 57.738,62.787 58.256,63.305 T2.49@60.615,63.305
  Bottom Layer w0.4: v1(12.5,102.5) 19.626,102.5 v1(24.48,97.646)
  Bottom Layer w0.6: v2(46.163,80) 46.163,92.41 v2(48.6,94.847) ; v2(55.7,26.1) 55.7,35.3 58.801,38.401 58.801,41.924 ; v1(57.5,41.924) 58.801,41.924 ; v1(57.7,61.705) 58.801,61.705 ; v2(58.8,70.3) 58.801,61.705 ; 58.801,41.924 58.801,61.705
+5VDD: C14.2 C15.1 C16.2 C18.1 C20.2 C21.2 LM1.3 LM1.4 LM2.3 R38.1 TCA1.1 TLC1.8 TLC2.4 TPS1.13 TPS1.14 TPS1.15 TPS1.16 | length 150.5
  Top Layer w0.254: 28.128,14.096 R38.1@28.128,15.3
  Top Layer w0.5: TPS1.13@18.95,22.025 21.707,22.025 22,21.732 C14.2@22,20.5 C16.2@22,18.6 22,16.95 ; LM1.4@20.823,16.95 22,16.95 ; LM1.3@23.223,16.95 22,16.95 ; LM2.3@58.24,21.2 58.24,18.24 56.8,16.8 48.7,16.8 45,13.1 42.404,13.1 31.2,13.1 30.204,14.096 28.128,14.096 26.249,14.096 24.356,12.203 22.897,12.203 22,13.1 22,16.95
  Top Layer w0.6: C20.2@1.6,79.2 1.6,80.149 1.951,80.5 3.3,80.5 3.9,79.9 TCA1.1@3.9,79.17 6.13,79.17 7,78.3 7,73.28 12.1,68.18 12.1,37.791 9.102,34.793 C15.1@9.102,32.693 ; 15.288,25.5 TLC1.8@15.288,27.295 ; TPS1.13@18.95,22.1 TPS1.14@18.95,22.675 ; TLC2.4@38.7,19.11 37.138,19.11 36.787,18.759 36.787,14.592 37.138,14.241 C21.2@42.404,14.241 42.404,13.1 ; LM2.3@58.24,21.2 C18.1@60.325,21.2
  Top Layer w0.8: C15.1@9.102,32.693 9.102,27.998 11.6,25.5 15.288,25.5 17.9,25.5 18.95,24.45 TPS1.16@18.95,23.975 TPS1.15@18.95,23.325 TPS1.14@18.95,22.675
-5VDD: C13.1 C22.2 LM1.1 TLC2.11 | length 15.2
  Top Layer w0.6: LM1.1@23.223,15.05 26.15,15.05 28.3,17.2 C13.1@28.3,19.1 ; C22.2@28.3,20.9 C13.1@28.3,19.1 ; TLC2.11@33.8,19.11 33.795,19.105 28.305,19.105 C13.1@28.3,19.1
